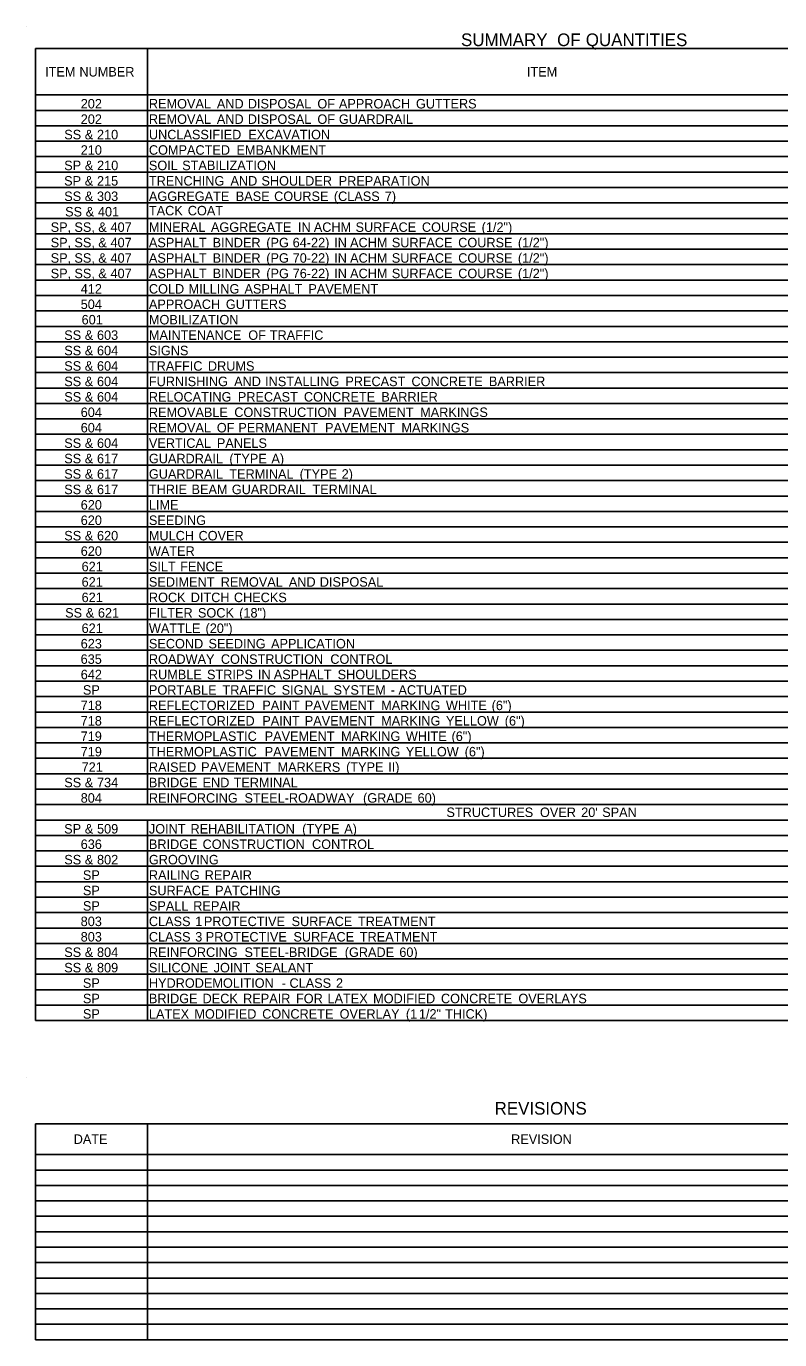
# Model space of a CAD drawing. Extents: x 544478 to 1930787, y -1948294 to 596640.
# Drawn here: x 546489 to 546965, y -1948185 to -1947354 of the extents above; entities that cross this region are included whole.
import ezdxf

# ---------------------------------------------------------------- set-up
doc = ezdxf.new("R2010")
doc.units = 0
doc.layers.add('Default', color=7, linetype='Continuous')

msp = doc.modelspace()

# ---------------------------------------------------------------- linework, layer by layer
at = {"layer": 'Default'}
for p, q in [((546489.25, -1947354.46), (546489.25, -1947354.46)), ((546495.1, -1947368.6), (547285.83, -1947368.6)), ((546495.1, -1947982.85), (546495.1, -1947368.6)), ((546495.1, -1947982.85), (546495.1, -1947368.6)), ((546565.79, -1947846.35), (546565.79, -1947368.6)), ((546495.1, -1947397.85), (547285.83, -1947397.85)), ((546495.1, -1947397.85), (547285.83, -1947397.85)), ((546565.79, -1947846.35), (546565.79, -1947397.85)), ((546495.1, -1947407.6), (547285.83, -1947407.6)), ((546495.1, -1947417.35), (547285.83, -1947417.35)), ((546495.1, -1947427.1), (547285.83, -1947427.1)), ((546495.1, -1947436.85), (547285.83, -1947436.85)), ((546495.1, -1947446.6), (547285.83, -1947446.6)), ((546495.1, -1947456.35), (547285.83, -1947456.35)), ((546495.1, -1947466.1), (547285.83, -1947466.1)), ((546495.1, -1947475.85), (547285.83, -1947475.85)), ((546495.1, -1947485.6), (547285.83, -1947485.6)), ((546495.1, -1947495.35), (547285.83, -1947495.35)), ((546495.1, -1947505.1), (547285.83, -1947505.1)), ((546495.1, -1947514.85), (547285.83, -1947514.85)), ((546495.1, -1947524.6), (547285.83, -1947524.6)), ((546495.1, -1947534.35), (547285.83, -1947534.35)), ((546495.1, -1947544.1), (547285.83, -1947544.1)), ((546495.1, -1947553.85), (547285.83, -1947553.85)), ((546495.1, -1947563.6), (547285.83, -1947563.6)), ((546495.1, -1947573.35), (547285.83, -1947573.35)), ((546495.1, -1947583.1), (547285.83, -1947583.1)), ((546495.1, -1947592.85), (547285.83, -1947592.85)), ((546495.1, -1947602.6), (547285.83, -1947602.6)), ((546495.1, -1947612.35), (547285.83, -1947612.35)), ((546495.1, -1947622.1), (547285.83, -1947622.1)), ((546495.1, -1947631.85), (547285.83, -1947631.85)), ((546495.1, -1947641.6), (547285.83, -1947641.6)), ((546495.1, -1947651.35), (547285.83, -1947651.35)), ((546495.1, -1947661.1), (547285.83, -1947661.1)), ((546495.1, -1947670.85), (547285.83, -1947670.85)), ((546495.1, -1947680.6), (547285.83, -1947680.6)), ((546495.1, -1947690.35), (547285.83, -1947690.35)), ((546495.1, -1947700.1), (547285.83, -1947700.1)), ((546495.1, -1947709.85), (547285.83, -1947709.85)), ((546495.1, -1947719.6), (547285.83, -1947719.6)), ((546495.1, -1947729.35), (547285.83, -1947729.35)), ((546495.1, -1947739.1), (547285.83, -1947739.1)), ((546495.1, -1947748.85), (547285.83, -1947748.85)), ((546495.1, -1947758.6), (547285.83, -1947758.6)), ((546495.1, -1947768.35), (547285.83, -1947768.35)), ((546495.1, -1947778.1), (547285.83, -1947778.1)), ((546495.1, -1947787.85), (547285.83, -1947787.85)), ((546495.1, -1947797.6), (547285.83, -1947797.6)), ((546495.1, -1947807.35), (547285.83, -1947807.35)), ((546495.1, -1947817.1), (547285.83, -1947817.1)), ((546495.1, -1947826.85), (547285.83, -1947826.85)), ((546495.1, -1947836.6), (547285.83, -1947836.6)), ((546495.1, -1947846.35), (547285.83, -1947846.35)), ((546495.1, -1947846.35), (547285.83, -1947846.35)), ((546495.1, -1947856.1), (547285.83, -1947856.1)), ((546495.1, -1947856.1), (547122.03, -1947856.1)), ((546565.79, -1947982.85), (546565.79, -1947856.1)), ((546565.79, -1947982.85), (546565.79, -1947856.1)), ((546495.1, -1947865.85), (547285.83, -1947865.85)), ((546495.1, -1947875.6), (547285.83, -1947875.6)), ((546495.1, -1947885.35), (547285.83, -1947885.35)), ((546495.1, -1947895.1), (547285.83, -1947895.1)), ((546495.1, -1947904.85), (547285.83, -1947904.85)), ((546495.1, -1947914.6), (547285.83, -1947914.6)), ((546495.1, -1947924.35), (547285.83, -1947924.35)), ((546495.1, -1947934.1), (547285.83, -1947934.1)), ((546495.1, -1947943.85), (547285.83, -1947943.85)), ((546495.1, -1947953.6), (547285.83, -1947953.6)), ((546495.1, -1947963.35), (547285.83, -1947963.35)), ((546495.1, -1947973.1), (547285.83, -1947973.1)), ((546495.1, -1947982.85), (547285.83, -1947982.85)), ((546489.25, -1948018.81), (546489.25, -1948018.81)), ((546495.1, -1948048.06), (547285.83, -1948048.06)), ((546495.1, -1948048.06), (546565.79, -1948048.06)), ((546495.1, -1948184.56), (546495.1, -1948048.06)), ((546495.1, -1948184.56), (546495.1, -1948048.06)), ((546565.79, -1948184.56), (546565.79, -1948048.06)), ((546495.1, -1948067.56), (547285.83, -1948067.56)), ((546495.1, -1948077.31), (547285.83, -1948077.31)), ((546495.1, -1948087.06), (547285.83, -1948087.06)), ((546495.1, -1948096.81), (547285.83, -1948096.81)), ((546495.1, -1948106.56), (547285.83, -1948106.56)), ((546495.1, -1948116.31), (547285.83, -1948116.31)), ((546495.1, -1948126.06), (547285.83, -1948126.06)), ((546495.1, -1948135.81), (547285.83, -1948135.81)), ((546495.1, -1948145.56), (547285.83, -1948145.56)), ((546495.1, -1948155.31), (547285.83, -1948155.31)), ((546495.1, -1948165.06), (547285.83, -1948165.06)), ((546495.1, -1948174.81), (547285.83, -1948174.81)), ((546495.1, -1948184.56), (547285.83, -1948184.56))]:
    msp.add_line(p, q, dxfattribs=at)

# ---------------------------------------------------------------- texts
for s, height, p in [('SUMMARY', 8, (546764.02, -1947367)), (' OF', 8, (546821.79, -1947367)), (' QUANTITIES', 8, (546839.9, -1947367)), ('ITEM', 6, (546501.19, -1947386.22)), (' NUMBER', 6, (546520.62, -1947386.22)), ('ITEM', 6, (546805.68, -1947386.22)), ('202', 6, (546523.68, -1947406.4)), ('REMOVAL', 6, (546566.76, -1947406.4)), (' AND', 6, (546607.47, -1947406.4)), (' DISPOSAL', 6, (546627.05, -1947406.4)), (' OF', 6, (546671.01, -1947406.4)), (' APPROACH', 6, (546684.6, -1947406.4)), (' GUTTERS', 6, (546733.31, -1947406.4)), ('202', 6, (546523.68, -1947416.15)), ('REMOVAL', 6, (546566.76, -1947416.15)), (' AND', 6, (546607.47, -1947416.15)), (' DISPOSAL', 6, (546627.05, -1947416.15)), (' OF', 6, (546671.01, -1947416.15)), (' GUARDRAIL', 6, (546684.6, -1947416.15)), ('SS', 6, (546513.26, -1947425.9)), (' &', 6, (546524, -1947425.9)), (' 210', 6, (546531.73, -1947425.9)), ('UNCLASSIFIED', 6, (546566.76, -1947425.9)), (' EXCAVATION', 6, (546627.35, -1947425.9)), ('210', 6, (546523.66, -1947435.65)), ('COMPACTED', 6, (546566.76, -1947435.65)), (' EMBANKMENT', 6, (546619.89, -1947435.65)), ('SP', 6, (546513.22, -1947445.4)), (' &', 6, (546524.04, -1947445.4)), (' 210', 6, (546531.77, -1947445.4)), ('SOIL', 6, (546566.76, -1947445.4)), (' STABILIZATION', 6, (546585.57, -1947445.4)), ('SP', 6, (546513.18, -1947455.15)), (' &', 6, (546524, -1947455.15)), (' 215', 6, (546531.73, -1947455.15)), ('TRENCHING', 6, (546566.76, -1947455.15)), (' AND', 6, (546616.08, -1947455.15)), (' SHOULDER', 6, (546635.66, -1947455.15)), (' PREPARATION', 6, (546684.46, -1947455.15)), ('SS', 6, (546513.24, -1947464.9)), (' &', 6, (546523.99, -1947464.9)), (' 303', 6, (546531.72, -1947464.9)), ('AGGREGATE', 6, (546566.76, -1947464.9)), (' BASE', 6, (546619.43, -1947464.9)), (' COURSE', 6, (546643.68, -1947464.9)), (' (CLASS', 6, (546681.43, -1947464.9)), (' 7)', 6, (546713.6, -1947464.9)), ('TACK', 6, (546566.76, -1947473.97)), (' COAT', 6, (546589.11, -1947473.97)), ('SS', 6, (546513.82, -1947474.65)), (' &', 6, (546524.57, -1947474.65)), (' 401', 6, (546532.3, -1947474.65)), ('SP,', 6, (546504.68, -1947484.4)), (' SS,', 6, (546517.45, -1947484.4)), (' &', 6, (546532.55, -1947484.4)), (' 407', 6, (546540.28, -1947484.4)), ('MINERAL', 6, (546566.76, -1947484.4)), (' AGGREGATE', 6, (546603.73, -1947484.4)), (' IN', 6, (546658.73, -1947484.4)), (' ACHM', 6, (546668.75, -1947484.4)), (' SURFACE', 6, (546695.13, -1947484.4)), (' COURSE', 6, (546737.08, -1947484.4)), (' (1/2")', 6, (546774.83, -1947484.4)), ('SP,', 6, (546504.68, -1947494.15)), (' SS,', 6, (546517.45, -1947494.15)), (' &', 6, (546532.55, -1947494.15)), (' 407', 6, (546540.28, -1947494.15)), ('ASPHALT', 6, (546566.76, -1947494.15)), (' BINDER', 6, (546604.8, -1947494.15)), (' (PG', 6, (546638.7, -1947494.15)), (' 64-22)', 6, (546655.4, -1947494.15)), (' IN', 6, (546681.65, -1947494.15)), (' ACHM', 6, (546691.67, -1947494.15)), (' SURFACE', 6, (546718.05, -1947494.15)), (' COURSE', 6, (546760, -1947494.15)), (' (1/2")', 6, (546797.75, -1947494.15)), ('SP,', 6, (546504.68, -1947503.9)), (' SS,', 6, (546517.45, -1947503.9)), (' &', 6, (546532.55, -1947503.9)), (' 407', 6, (546540.28, -1947503.9)), ('ASPHALT', 6, (546566.76, -1947503.9)), (' BINDER', 6, (546604.8, -1947503.9)), (' (PG', 6, (546638.7, -1947503.9)), (' 70-22)', 6, (546655.4, -1947503.9)), (' IN', 6, (546681.65, -1947503.9)), (' ACHM', 6, (546691.67, -1947503.9)), (' SURFACE', 6, (546718.05, -1947503.9)), (' COURSE', 6, (546760, -1947503.9)), (' (1/2")', 6, (546797.75, -1947503.9)), ('SP,', 6, (546504.68, -1947513.65)), (' SS,', 6, (546517.45, -1947513.65)), (' &', 6, (546532.55, -1947513.65)), (' 407', 6, (546540.28, -1947513.65)), ('ASPHALT', 6, (546566.76, -1947513.65)), (' BINDER', 6, (546604.8, -1947513.65)), (' (PG', 6, (546638.7, -1947513.65)), (' 76-22)', 6, (546655.4, -1947513.65)), (' IN', 6, (546681.65, -1947513.65)), (' ACHM', 6, (546691.67, -1947513.65)), (' SURFACE', 6, (546718.05, -1947513.65)), (' COURSE', 6, (546760, -1947513.65)), (' (1/2")', 6, (546797.75, -1947513.65)), ('412', 6, (546523.68, -1947523.4)), ('COLD', 6, (546566.76, -1947523.4)), (' MILLING', 6, (546589.61, -1947523.4)), (' ASPHALT', 6, (546624.94, -1947523.4)), (' PAVEMENT', 6, (546665.31, -1947523.4)), ('504', 6, (546523.66, -1947533.15)), ('APPROACH', 6, (546566.76, -1947533.15)), (' GUTTERS', 6, (546613.15, -1947533.15)), ('601', 6, (546524.23, -1947542.9)), ('MOBILIZATION', 6, (546566.76, -1947542.9)), ('SS', 6, (546513.24, -1947552.65)), (' &', 6, (546523.99, -1947552.65)), (' 603', 6, (546531.72, -1947552.65)), ('MAINTENANCE', 6, (546566.76, -1947552.65)), (' OF', 6, (546627.34, -1947552.65)), (' TRAFFIC', 6, (546640.93, -1947552.65)), ('SS', 6, (546513.26, -1947562.4)), (' &', 6, (546524, -1947562.4)), (' 604', 6, (546531.73, -1947562.4)), ('SIGNS', 6, (546566.76, -1947562.4)), ('SS', 6, (546513.26, -1947572.15)), (' &', 6, (546524, -1947572.15)), (' 604', 6, (546531.73, -1947572.15)), ('TRAFFIC', 6, (546566.76, -1947572.15)), (' DRUMS', 6, (546601.83, -1947572.15)), ('SS', 6, (546513.26, -1947581.9)), (' 604', 6, (546531.73, -1947581.9)), ('FURNISHING', 6, (546566.76, -1947581.9)), (' INSTALLING', 6, (546637.99, -1947581.9)), (' PRECAST', 6, (546688.7, -1947581.9)), (' CONCRETE', 6, (546730.47, -1947581.9)), (' &', 6, (546524, -1947581.9)), (' AND', 6, (546618.4, -1947581.9)), (' BARRIER', 6, (546779.39, -1947581.9)), ('SS', 6, (546513.26, -1947591.65)), (' &', 6, (546524, -1947591.65)), (' 604', 6, (546531.73, -1947591.65)), ('RELOCATING', 6, (546566.76, -1947591.65)), (' PRECAST', 6, (546620.74, -1947591.65)), (' CONCRETE', 6, (546662.5, -1947591.65)), (' BARRIER', 6, (546711.43, -1947591.65)), ('604', 6, (546523.66, -1947601.4)), ('REMOVABLE', 6, (546566.76, -1947601.4)), (' CONSTRUCTION', 6, (546618.5, -1947601.4)), (' PAVEMENT', 6, (546687.68, -1947601.4)), (' MARKINGS', 6, (546735.96, -1947601.4)), ('604', 6, (546523.66, -1947611.15)), ('REMOVAL', 6, (546566.76, -1947611.15)), (' OF', 6, (546607.47, -1947611.15)), (' PERMANENT', 6, (546621.05, -1947611.15)), (' PAVEMENT', 6, (546675.85, -1947611.15)), (' MARKINGS', 6, (546724.14, -1947611.15)), ('SS', 6, (546513.26, -1947620.9)), (' &', 6, (546524, -1947620.9)), (' 604', 6, (546531.73, -1947620.9)), ('VERTICAL', 6, (546566.76, -1947620.9)), (' PANELS', 6, (546607.47, -1947620.9)), ('SS', 6, (546513.24, -1947630.65)), (' &', 6, (546523.99, -1947630.65)), (' 617', 6, (546531.72, -1947630.65)), ('GUARDRAIL', 6, (546566.76, -1947630.65)), (' (TYPE', 6, (546615.38, -1947630.65)), (' A)', 6, (546641.95, -1947630.65)), ('SS', 6, (546513.24, -1947640.4)), (' &', 6, (546523.99, -1947640.4)), (' 617', 6, (546531.72, -1947640.4)), ('GUARDRAIL', 6, (546566.76, -1947640.4)), (' TERMINAL', 6, (546615.38, -1947640.4)), (' (TYPE', 6, (546659.8, -1947640.4)), (' 2)', 6, (546686.37, -1947640.4)), ('SS', 6, (546513.24, -1947650.15)), (' &', 6, (546523.99, -1947650.15)), (' 617', 6, (546531.72, -1947650.15)), ('THRIE', 6, (546566.76, -1947650.15)), (' BEAM', 6, (546591.47, -1947650.15)), (' GUARDRAIL', 6, (546616.93, -1947650.15)), (' TERMINAL', 6, (546667.87, -1947650.15)), ('620', 6, (546523.66, -1947659.9)), ('LIME', 6, (546566.76, -1947659.9)), ('620', 6, (546523.66, -1947669.65)), ('SEEDING', 6, (546566.76, -1947669.65)), ('SS', 6, (546513.26, -1947679.4)), (' &', 6, (546524, -1947679.4)), (' 620', 6, (546531.73, -1947679.4)), ('MULCH', 6, (546566.76, -1947679.4)), (' COVER', 6, (546595.9, -1947679.4)), ('620', 6, (546523.66, -1947689.15)), ('WATER', 6, (546566.76, -1947689.15)), ('621', 6, (546524.23, -1947698.9)), ('SILT', 6, (546566.76, -1947698.9)), (' FENCE', 6, (546584.3, -1947698.9)), ('621', 6, (546524.23, -1947708.65)), ('SEDIMENT', 6, (546566.76, -1947708.65)), (' REMOVAL', 6, (546609.92, -1947708.65)), (' AND', 6, (546652.95, -1947708.65)), (' DISPOSAL', 6, (546672.53, -1947708.65)), ('621', 6, (546524.23, -1947718.4)), ('ROCK', 6, (546566.76, -1947718.4)), (' DITCH', 6, (546590.97, -1947718.4)), (' CHECKS', 6, (546618.24, -1947718.4)), ('SS', 6, (546513.82, -1947728.15)), (' &', 6, (546524.57, -1947728.15)), (' 621', 6, (546532.3, -1947728.15)), ('FILTER', 6, (546566.76, -1947728.15)), (' SOCK', 6, (546595.53, -1947728.15)), (' (18")', 6, (546621.6, -1947728.15)), ('621', 6, (546524.23, -1947737.9)), ('WATTLE', 6, (546566.76, -1947737.9)), (' (20")', 6, (546600.32, -1947737.9)), ('623', 6, (546523.65, -1947747.65)), ('SECOND', 6, (546566.76, -1947747.65)), (' SEEDING', 6, (546602.19, -1947747.65)), (' APPLICATION', 6, (546641.73, -1947747.65)), ('635', 6, (546523.62, -1947757.4)), ('ROADWAY', 6, (546566.76, -1947757.4)), (' CONSTRUCTION', 6, (546610.02, -1947757.4)), (' CONTROL', 6, (546679.2, -1947757.4)), ('642', 6, (546523.68, -1947767.15)), ('RUMBLE', 6, (546566.76, -1947767.15)), (' STRIPS', 6, (546601.26, -1947767.15)), (' IN', 6, (546633.43, -1947767.15)), (' ASPHALT', 6, (546643.45, -1947767.15)), (' SHOULDERS', 6, (546683.82, -1947767.15)), ('SP', 6, (546525.04, -1947776.9)), ('PORTABLE', 6, (546566.76, -1947776.9)), (' TRAFFIC', 6, (546611.05, -1947776.9)), (' SIGNAL', 6, (546648.44, -1947776.9)), (' SYSTEM', 6, (546681.22, -1947776.9)), (' -', 6, (546717.39, -1947776.9)), (' ACTUATED', 6, (546722.25, -1947776.9)), ('718', 6, (546523.64, -1947786.65)), ('REFLECTORIZED', 6, (546566.76, -1947786.65)), (' PAINT', 6, (546636.19, -1947786.65)), (' PAVEMENT', 6, (546663.04, -1947786.65)), (' MARKING', 6, (546711.32, -1947786.65)), (' WHITE', 6, (546752.25, -1947786.65)), (' (6")', 6, (546781.14, -1947786.65)), ('718', 6, (546523.64, -1947796.4)), ('REFLECTORIZED', 6, (546566.76, -1947796.4)), (' PAINT', 6, (546636.19, -1947796.4)), (' PAVEMENT', 6, (546663.04, -1947796.4)), (' MARKING', 6, (546711.32, -1947796.4)), (' YELLOW', 6, (546752.25, -1947796.4)), (' (6")', 6, (546789.42, -1947796.4)), (' (6")', 6, (546755.81, -1947806.15)), ('719', 6, (546523.64, -1947806.15)), ('THERMOPLASTIC', 6, (546566.76, -1947806.15)), (' PAVEMENT', 6, (546637.7, -1947806.15)), (' MARKING', 6, (546685.99, -1947806.15)), (' WHITE', 6, (546726.92, -1947806.15)), ('719', 6, (546523.64, -1947815.9)), ('THERMOPLASTIC', 6, (546566.76, -1947815.9)), (' PAVEMENT', 6, (546637.7, -1947815.9)), (' MARKING', 6, (546685.99, -1947815.9)), (' YELLOW', 6, (546726.92, -1947815.9)), (' (6")', 6, (546764.09, -1947815.9)), ('721', 6, (546524.23, -1947825.65)), ('RAISED', 6, (546566.76, -1947825.65)), (' PAVEMENT', 6, (546597.53, -1947825.65)), (' MARKERS', 6, (546645.82, -1947825.65)), (' (TYPE', 6, (546689.17, -1947825.65)), (' II)', 6, (546715.74, -1947825.65)), ('SS', 6, (546513.26, -1947835.4)), (' &', 6, (546524, -1947835.4)), (' 734', 6, (546531.73, -1947835.4)), ('BRIDGE', 6, (546566.76, -1947835.4)), (' END', 6, (546598.46, -1947835.4)), (' TERMINAL', 6, (546618.04, -1947835.4)), ('804', 6, (546523.66, -1947845.15)), ('REINFORCING', 6, (546566.76, -1947845.15)), (' STEEL-ROADWAY', 6, (546624.93, -1947845.15)), (' (GRADE', 6, (546699.86, -1947845.15)), (' 60)', 6, (546734.35, -1947845.15)), ('STRUCTURES', 6, (546754.81, -1947854.22)), (' OVER', 6, (546811.69, -1947854.22)), (" 20'", 6, (546837.74, -1947854.22)), (' SPAN', 6, (546851.02, -1947854.22)), ('SP', 6, (546513.2, -1947864.65)), (' &', 6, (546524.02, -1947864.65)), (' 509', 6, (546531.75, -1947864.65)), ('JOINT', 6, (546566.76, -1947864.65)), (' REHABILITATION', 6, (546590.81, -1947864.65)), (' (TYPE', 6, (546661.4, -1947864.65)), (' A)', 6, (546687.97, -1947864.65)), ('636', 6, (546523.65, -1947874.4)), ('BRIDGE', 6, (546566.76, -1947874.4)), (' CONSTRUCTION', 6, (546598.46, -1947874.4)), (' CONTROL', 6, (546667.64, -1947874.4)), ('SS', 6, (546513.28, -1947884.15)), (' &', 6, (546524.02, -1947884.15)), (' 802', 6, (546531.75, -1947884.15)), ('GROOVING', 6, (546566.76, -1947884.15)), ('SP', 6, (546525.04, -1947893.9)), ('RAILING', 6, (546566.76, -1947893.9)), (' REPAIR', 6, (546599.78, -1947893.9)), ('SP', 6, (546525.04, -1947903.65)), ('SURFACE', 6, (546566.76, -1947903.65)), (' PATCHING', 6, (546606.38, -1947903.65)), ('SP', 6, (546525.04, -1947913.4)), ('SPALL', 6, (546566.76, -1947913.4)), (' REPAIR', 6, (546592.57, -1947913.4)), ('803', 6, (546523.65, -1947923.15)), ('CLASS', 6, (546566.76, -1947923.15)), (' 1', 6, (546593.82, -1947923.15)), (' PROTECTIVE', 6, (546599.27, -1947923.15)), (' SURFACE', 6, (546654.72, -1947923.15)), (' TREATMENT', 6, (546696.67, -1947923.15)), ('803', 6, (546523.65, -1947932.9)), ('CLASS', 6, (546566.76, -1947932.9)), (' 3', 6, (546593.82, -1947932.9)), (' PROTECTIVE', 6, (546600.43, -1947932.9)), (' SURFACE', 6, (546655.88, -1947932.9)), (' TREATMENT', 6, (546697.83, -1947932.9)), ('SS', 6, (546513.26, -1947942.65)), (' &', 6, (546524, -1947942.65)), (' 804', 6, (546531.73, -1947942.65)), ('REINFORCING', 6, (546566.76, -1947942.65)), (' STEEL-BRIDGE', 6, (546624.93, -1947942.65)), (' (GRADE', 6, (546688.3, -1947942.65)), (' 60)', 6, (546722.79, -1947942.65)), ('SS', 6, (546513.24, -1947952.4)), (' &', 6, (546523.99, -1947952.4)), (' 809', 6, (546531.71, -1947952.4)), ('SILICONE', 6, (546566.76, -1947952.4)), (' JOINT', 6, (546605.45, -1947952.4)), (' SEALANT', 6, (546631.83, -1947952.4)), ('SP', 6, (546525.04, -1947962.15)), ('HYDRODEMOLITION', 6, (546566.76, -1947962.15)), (' CLASS', 6, (546653.38, -1947962.15)), (' 2', 6, (546682.76, -1947962.15)), ('SP', 6, (546525.04, -1947971.9)), ('BRIDGE', 6, (546566.76, -1947971.9)), (' DECK', 6, (546598.46, -1947971.9)), (' REPAIR', 6, (546624.07, -1947971.9)), (' -', 6, (546648.52, -1947962.15)), (' FOR', 6, (546657.5, -1947971.9)), (' LATEX', 6, (546677.41, -1947971.9)), (' MODIFIED', 6, (546706.24, -1947971.9)), (' CONCRETE', 6, (546749.11, -1947971.9)), (' OVERLAYS', 6, (546798.03, -1947971.9)), ('SP', 6, (546525.04, -1947981.65)), ('LATEX', 6, (546566.76, -1947981.65)), (' MODIFIED', 6, (546593.27, -1947981.65)), (' CONCRETE', 6, (546636.13, -1947981.65)), (' OVERLAY', 6, (546685.06, -1947981.65)), (' (1', 6, (546726.94, -1947981.65)), (' 1/2"', 6, (546735.17, -1947981.65)), (' THICK)', 6, (546751.73, -1947981.65)), ('REVISIONS', 8, (546785.22, -1948042.31)), ('DATE', 6, (546519.24, -1948060.81)), ('REVISION', 6, (546795.69, -1948060.81))]:
    msp.add_text(s, height=height, dxfattribs=at).set_placement(p)

doc.saveas('drawing.dxf')
